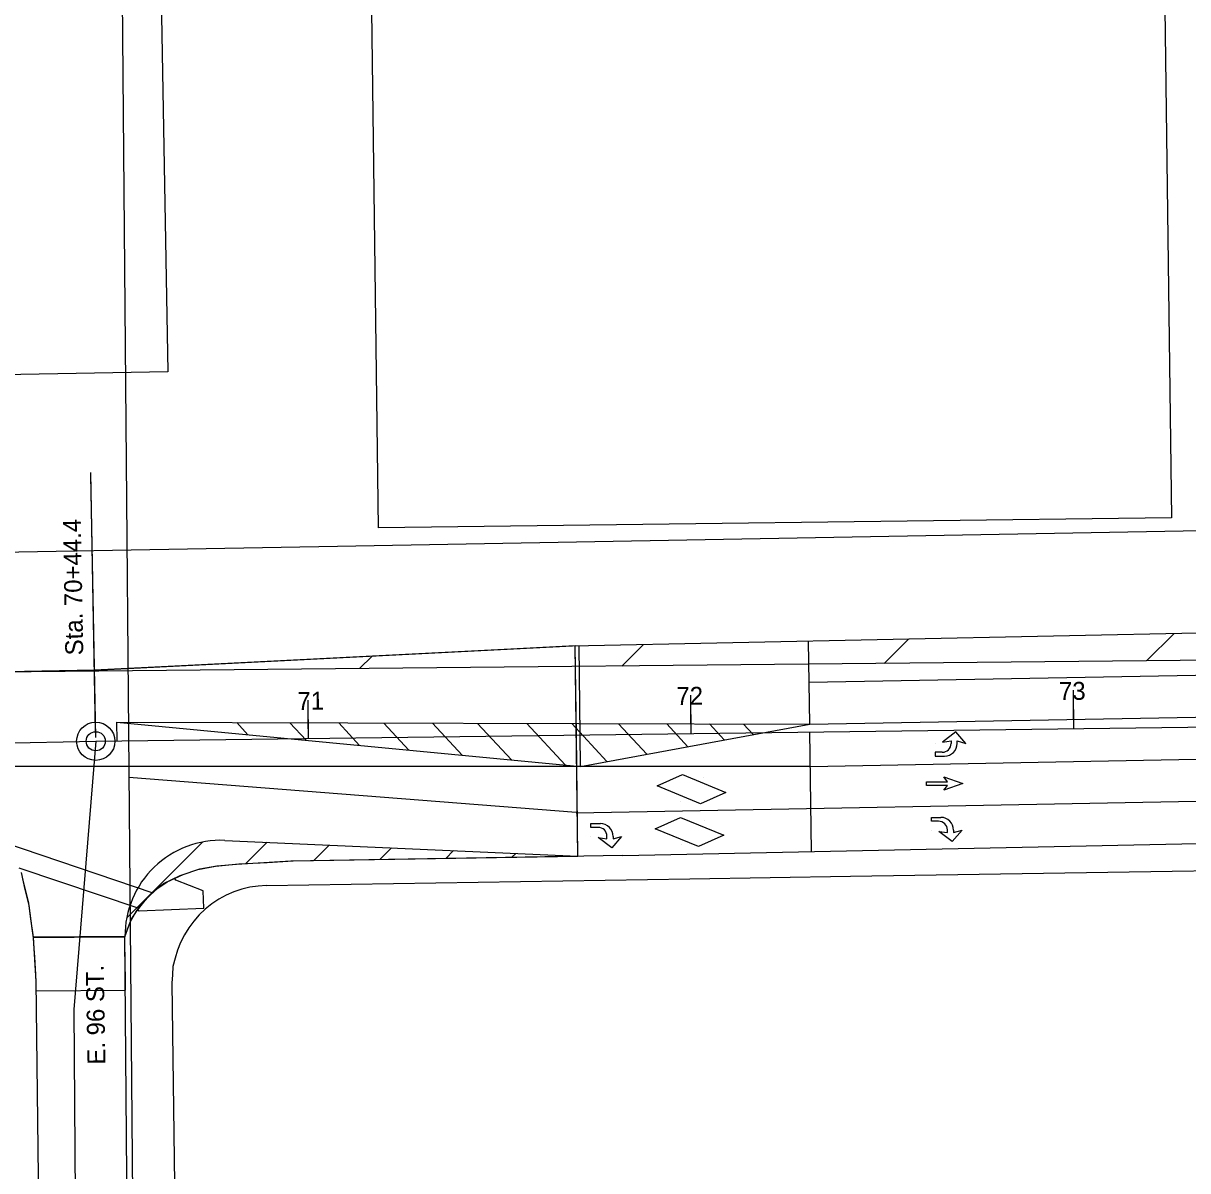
# Model space of a CAD drawing. Extents: x -2233 to 187241, y 4582 to 150524.
# Drawn here: x 106968.6 to 107272.9, y 59338.1 to 59637.9 of the extents above; entities that cross this region are included whole.
import ezdxf

# ---------------------------------------------------------------- set-up
doc = ezdxf.new("R2010")
doc.units = 0
for name, color, linetype in [('AP_X_Misc', 7, 'Continuous'), ('BLDG', 7, 'Continuous'), ('GE_X_CL_100', 7, 'Continuous'), ('GE_X_CL_20', 7, 'Continuous'), ('GE_X_CL_2000', 7, 'Continuous'), ('GE_X_CL_50', 7, 'Continuous'), ('GRID', 7, 'Continuous'), ('PM_P_Cells', 7, 'Continuous'), ('PM_P_Channelizing_Line', 7, 'Continuous'), ('PM_P_CL_Double_Solid', 7, 'Continuous'), ('PM_P_Crosswalk', 7, 'Continuous'), ('PM_P_Edge_Line', 7, 'Continuous'), ('PM_P_Lane_Line', 7, 'Continuous'), ('PM_P_Text', 7, 'Continuous'), ('PM_P_Transverse_Line', 7, 'Continuous'), ('PV_P_Curb_Ramp', 7, 'Continuous'), ('ROAD', 7, 'Continuous'), ('RW_X_Fee_RW', 7, 'Continuous'), ('SG_P_Detection', 7, 'Continuous')]:
    doc.layers.add(name, color=color, linetype=linetype)

msp = doc.modelspace()

# ---------------------------------------------------------------- linework, layer by layer
at = {"layer": 'AP_X_Misc'}
for p, q in [((107113.16, 59451.93), (107112.85, 59475.22)), ((107113.57, 59420.27), (107113.16, 59451.93))]:
    msp.add_line(p, q, dxfattribs=at)
at = {"layer": 'BLDG'}
for points in [[(107138.05, 59845.37), (107137.53, 59885.63), (107205.31, 59886.51), (107205.83, 59846.29), (107219.12, 59846.47), (107220.3, 59754.44), (107265.47, 59755.03), (107268.65, 59508.72), (107061.45, 59506.05), (107057.09, 59844.32)], [(107001.39, 59825.86), (107006.43, 59546.84), (106886.38, 59544.66), (106881.33, 59823.69)]]:
    msp.add_lwpolyline(points, close=True, dxfattribs=at)
at = {"layer": 'GE_X_CL_100'}
for p, q in [((107143.15, 59452.32), (107143.02, 59462.32)), ((107243.14, 59453.61), (107243.01, 59463.61)), ((107043.16, 59451.02), (107043.03, 59461.02))]:
    msp.add_line(p, q, dxfattribs=at)
msp.add_circle((106987.56, 59450.3), 5, dxfattribs=at)
at = {"layer": 'GE_X_CL_20'}
for p, q in [((106987.56, 59450.3), (107446.21, 59456.25)), ((106347.67, 59438.51), (106987.56, 59450.3)), ((106987.56, 59450.3), (106981.87, 59380.16)), ((106981.87, 59380.16), (106982.24, 59327.03))]:
    msp.add_line(p, q, dxfattribs=at)
at = {"layer": 'GE_X_CL_2000'}
for p, q in [((106987.56, 59450.3), (107446.21, 59456.25)), ((106347.67, 59438.51), (106987.56, 59450.3))]:
    msp.add_line(p, q, dxfattribs=at)
at = {"layer": 'GE_X_CL_50'}
for p, q in [((106987.51, 59452.8), (106986.26, 59520.58)), ((107243.14, 59453.61), (107243.08, 59458.61)), ((107043.16, 59451.02), (107043.1, 59456.02)), ((107143.15, 59452.32), (107143.09, 59457.32))]:
    msp.add_line(p, q, dxfattribs=at)
msp.add_circle((106987.56, 59450.3), 2.5, dxfattribs=at)
at = {"layer": 'GRID'}
msp.add_line((106991.2, 60017.41), (107014.74, 57319.74), dxfattribs=at)
at = {"layer": 'PM_P_Cells'}
for p, q in [((107212.33, 59452.75), (107208.81, 59450.08)), ((107214.89, 59449.75), (107212.33, 59452.75)), ((107206.89, 59449.75), (107206.89, 59449.75)), ((107208.81, 59450.08), (107211.05, 59450.41)), ((107211.05, 59450.41), (107211.05, 59449.71)), ((107212.65, 59449.75), (107212.65, 59450.41)), ((107212.65, 59450.41), (107214.89, 59449.75)), ((107214.89, 59449.75), (107214.89, 59449.75)), ((107208.75, 59447.41), (107206.89, 59447.41)), ((107206.89, 59447.41), (107206.89, 59446.41)), ((107206.89, 59446.41), (107209.37, 59446.41)), ((107210.16, 59439.72), (107209.16, 59440.96)), ((107209.16, 59440.96), (107214.16, 59439.22)), ((107204.66, 59438.72), (107204.66, 59439.72)), ((107204.66, 59439.72), (107210.16, 59439.72)), ((107204.66, 59439.22), (107204.66, 59439.22)), ((107210.16, 59438.72), (107204.66, 59438.72)), ((107214.16, 59439.22), (107209.16, 59437.48)), ((107209.16, 59437.48), (107210.16, 59438.72)), ((107214.16, 59439.22), (107214.16, 59439.22)), ((107116.96, 59427.77), (107116.96, 59428.77)), ((107116.96, 59428.77), (107119.44, 59428.77)), ((107118.83, 59427.77), (107116.96, 59427.77)), ((107205.93, 59429.41), (107205.93, 59430.41)), ((107205.93, 59430.41), (107208.4, 59430.41)), ((107207.79, 59429.41), (107205.93, 59429.41)), ((107116.96, 59425.44), (107116.96, 59425.44)), ((107122.4, 59422.44), (107118.88, 59425.11)), ((107118.88, 59425.11), (107121.12, 59424.77)), ((107121.12, 59424.77), (107121.12, 59425.48)), ((107124.96, 59425.44), (107122.4, 59422.44)), ((107122.72, 59425.44), (107122.72, 59424.77)), ((107122.72, 59424.77), (107124.96, 59425.44)), ((107124.96, 59425.44), (107124.96, 59425.44)), ((107205.93, 59427.07), (107205.93, 59427.07)), ((107211.37, 59424.07), (107207.85, 59426.74)), ((107207.85, 59426.74), (107210.09, 59426.41)), ((107210.09, 59426.41), (107210.09, 59427.11)), ((107213.93, 59427.07), (107211.37, 59424.07)), ((107211.69, 59427.07), (107211.69, 59426.41)), ((107211.69, 59426.41), (107213.93, 59427.07)), ((107213.93, 59427.07), (107213.93, 59427.07))]:
    msp.add_line(p, q, dxfattribs=at)
for centre, radius, start, end in [((107208.75, 59449.71), 2.3, 270, 0), ((107209.37, 59449.69), 3.28, 270, 0.9085), ((107118.83, 59425.48), 2.3, 0, 90), ((107119.44, 59425.49), 3.28, 359.0915, 90), ((107207.79, 59427.11), 2.3, 0, 90), ((107208.4, 59427.12), 3.28, 359.0915, 90)]:
    msp.add_arc(centre, radius, start, end, dxfattribs=at)
at = {"layer": 'PM_P_Channelizing_Line'}
for p, q in [((107174.27, 59443.73), (107380.24, 59447.55)), ((107113.13, 59431.59), (107380.38, 59436.56))]:
    msp.add_line(p, q, dxfattribs=at)
at = {"layer": 'PM_P_CL_Double_Solid'}
for p, q in [((107174.12, 59454.73), (107380.09, 59458.55)), ((106993.08, 59455.26), (107174.12, 59454.73)), ((106993.08, 59455.26), (107114.26, 59443.73)), ((107114.26, 59443.73), (107174.12, 59454.73))]:
    msp.add_line(p, q, dxfattribs=at)
at = {"layer": 'PM_P_Crosswalk'}
for p, q in [((106963.43, 59423.89), (107002.44, 59410.71)), ((106967.45, 59417.25), (106998.78, 59406.67))]:
    msp.add_line(p, q, dxfattribs=at)
at = {"layer": 'PM_P_Edge_Line'}
for p, q in [((107365.13, 59472.28), (106960.11, 59468.34)), ((107021.3, 59424.39), (107113.57, 59420.27))]:
    msp.add_line(p, q, dxfattribs=at)
msp.add_arc((107020.19, 59399.41), 25, 87.4436, 180.4769, dxfattribs=at)
at = {"layer": 'PM_P_Lane_Line'}
msp.add_line((106996.2, 59440.91), (107113.12, 59431.78), dxfattribs=at)
at = {"layer": 'PM_P_Text'}
for p, q in [((107174.12, 59454.73), (107173.84, 59476.48)), ((107114.15, 59451.94), (107113.85, 59475.24)), ((107173.98, 59465.73), (107389.95, 59469.74)), ((106993.16, 59450.4), (106993.08, 59455.26)), ((107174.56, 59421.49), (107174.15, 59452.72)), ((107114.26, 59443.73), (107114.15, 59451.94)), ((107174.27, 59443.73), (106960.1, 59443.73))]:
    msp.add_line(p, q, dxfattribs=at)
msp.add_lwpolyline([(106968.43, 59414.36), (106969.96, 59407.97), (106970.46, 59404.47), (106971.17, 59399.06), (106971.17, 59399.06), (106976.56, 59399.09), (106981.91, 59399.12), (106992.14, 59399.18), (106995.19, 59399.2), (106995.19, 59399.2), (106995.88, 59401.2), (106997.02, 59403.93), (106998.92, 59406.85), (107001.07, 59409.4), (107003.52, 59411.75), (107006.2, 59413.57), (107010.38, 59415.45), (107014.19, 59416.78), (107018.88, 59417.65), (107024.95, 59418.22), (107032.33, 59418.65), (107039.18, 59419.01), (107113.57, 59420.27), (107112.85, 59475.22), (107092.65, 59474.21), (107011.68, 59470.09), (106987.22, 59468.85), (106978.3, 59468.68), (106964.89, 59468.43)], dxfattribs=at)
msp.add_lwpolyline([(106971.51, 59393.86), (106971.8, 59389.3), (106971.91, 59387.13), (106971.93, 59385.07), (106995.31, 59385.2), (106995.29, 59387.36), (106995.24, 59392.79), (106995.2, 59397.68), (106995.2, 59399.24), (106971.17, 59399.06), (106971.36, 59396.15)], close=True, dxfattribs=at)
at = {"layer": 'PM_P_Transverse_Line'}
for p, q in [((107200.01, 59477.03), (107193.59, 59470.61)), ((107269.33, 59478.47), (107262.14, 59471.28)), ((107130.69, 59475.59), (107125.04, 59469.94)), ((107059.76, 59472.54), (107056.49, 59469.28)), ((106988.24, 59468.9), (106987.94, 59468.61)), ((107024.41, 59455.17), (107027.34, 59452)), ((107038.27, 59455.13), (107042.5, 59450.56)), ((107051.08, 59455.09), (107056.5, 59449.23)), ((107062.86, 59455.06), (107069.39, 59448)), ((107075.58, 59455.02), (107083.29, 59446.68)), ((107087.35, 59454.98), (107096.16, 59445.45)), ((107100.17, 59454.95), (107110.19, 59444.12)), ((107111.96, 59454.91), (107121.14, 59444.99)), ((107124.18, 59454.88), (107131.55, 59446.91)), ((107136.75, 59454.84), (107142.26, 59448.87)), ((107147.95, 59454.81), (107151.81, 59450.63)), ((107156.82, 59454.78), (107159.38, 59452.02)), ((106995.65, 59404.17), (107015.43, 59423.95)), ((107026.77, 59418.32), (107032.34, 59423.89)), ((107044.52, 59419.1), (107048.58, 59423.17)), ((107061.78, 59419.39), (107064.83, 59422.44)), ((107079.04, 59419.69), (107081.08, 59421.72)), ((107096.3, 59419.98), (107097.32, 59420.99))]:
    msp.add_line(p, q, dxfattribs=at)
at = {"layer": 'PV_P_Curb_Ramp'}
msp.add_lwpolyline([(106998.51, 59406.28), (106998.9, 59405.98), (107015.79, 59406.68), (107015.65, 59411.17), (107008.49, 59413.99), (107008.26, 59414.44), (107007, 59413.93), (107005.62, 59413.17), (107004.25, 59412.24), (107002.94, 59411.27), (107001.96, 59410.29), (107000.9, 59409.23), (107000.04, 59408.22), (106999.33, 59407.35), (106998.78, 59406.67)], close=True, dxfattribs=at)
at = {"layer": 'ROAD'}
for p, q in [((106987.54, 59451.3), (106986.28, 59519.84)), ((107112.12, 59475.2), (107376.26, 59480.69)), ((106987.22, 59468.85), (107112.12, 59475.2)), ((107125.33, 59420.46), (107367, 59425.49)), ((107024.37, 59418.18), (107038.54, 59419.02)), ((107125.33, 59420.46), (107038.54, 59419)), ((106968.07, 59416.02), (106969.03, 59411.57)), ((107009.6, 59415.18), (107014.77, 59416.98)), ((107014.77, 59416.98), (107019.21, 59417.7)), ((107019.21, 59417.7), (107024.37, 59418.18)), ((107003, 59411.33), (107005.28, 59413.14)), ((107005.28, 59413.14), (107009.6, 59415.18)), ((106969.03, 59411.57), (106970.11, 59407.37)), ((107000.72, 59409.05), (107003, 59411.33)), ((106970.11, 59407.37), (106970.83, 59401.36)), ((106998.08, 59405.81), (107000.72, 59409.05)), ((106996.52, 59403.05), (106998.08, 59405.81)), ((106970.83, 59401.36), (106971.19, 59398.96)), ((106995.19, 59399.2), (106996.52, 59403.05)), ((106971.17, 59399.06), (106995.19, 59399.2)), ((106971.93, 59385.07), (106995.31, 59385.2))]:
    msp.add_line(p, q, dxfattribs=at)
for points in [[(106987.22, 59468.85), (106978.05, 59468.68), (106497.52, 59459.55)], [(106971.19, 59398.96), (106971.9, 59387.59), (106974.68, 59154.2), (106978.12, 58882.39), (106982.23, 58497.46), (106991.01, 57977.54), (106989.93, 57970.29), (106987.11, 57964.18), (106982.47, 57958.48), (106976, 57955.07), (106963.82, 57952.33), (106872.79, 57947.8), (106677.99, 57941.78), (106511.5, 57935.89)], [(107004.75, 58202.22), (107001.77, 58609.08), (106995.19, 59399.2)]]:
    msp.add_lwpolyline(points, dxfattribs=at)
at = {"layer": 'RW_X_Fee_RW'}
for points in [[(106844.84, 59497.59), (107050.71, 59501.3), (107276.46, 59505.37)], [(107032.19, 59412.57), (107142.8, 59414.33), (107184.8, 59415), (107364.13, 59417.86)], [(107032.19, 59412.57), (107030.01, 59412.44), (107027.85, 59412.12), (107025.72, 59411.61), (107023.65, 59410.92), (107021.64, 59410.05), (107019.72, 59409.01), (107017.9, 59407.81), (107016.19, 59406.45), (107014.6, 59404.94), (107013.16, 59403.3), (107011.86, 59401.55), (107010.72, 59399.68), (107009.74, 59397.73), (107008.94, 59395.69), (107008.32, 59393.6), (107007.72, 59391.45), (107007.6, 59389.28), (107007.47, 59387.08)], [(107007.47, 59387.08), (107014.74, 58836.41), (107016.81, 58684.68), (107017.89, 58605.03)]]:
    msp.add_lwpolyline(points, dxfattribs=at)
at = {"layer": 'SG_P_Detection'}
for p, q in [((107134.29, 59438.63), (107140.89, 59441.62)), ((107140.89, 59441.62), (107152.21, 59436.94)), ((107146.39, 59440.71), (107146.39, 59440.71)), ((107145.61, 59433.95), (107134.29, 59438.63)), ((107152.21, 59436.94), (107145.61, 59433.95)), ((107140.47, 59434.6), (107140.47, 59434.6)), ((107133.72, 59427.43), (107140.32, 59430.41)), ((107140.32, 59430.41), (107151.64, 59425.74)), ((107146.53, 59429.53), (107146.53, 59429.53)), ((107145.04, 59422.75), (107133.72, 59427.43)), ((107151.64, 59425.74), (107145.04, 59422.75)), ((107140.61, 59423.4), (107140.61, 59423.4))]:
    msp.add_line(p, q, dxfattribs=at)

# ---------------------------------------------------------------- texts
at = {"layer": 'GE_X_CL_50'}
for s, rotation, p in [('Sta. 70+44.4', 91.0558, (106984.3, 59472.79)), ('72', 0.7431, (107139.32, 59459.77)), ('73', 0.7431, (107239.29, 59461.06)), ('71', 0.7431, (107040.28, 59458.48)), ('E. 96 ST.', 91.0558, (106990.1, 59365.82))]:
    msp.add_text(s, height=4.68, rotation=rotation, dxfattribs=at).set_placement(p)

doc.saveas('drawing.dxf')
